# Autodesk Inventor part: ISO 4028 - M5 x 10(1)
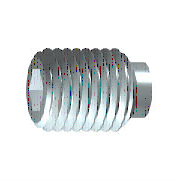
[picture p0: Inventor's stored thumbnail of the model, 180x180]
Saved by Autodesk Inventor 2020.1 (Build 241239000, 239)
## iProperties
Created: 2019-01
Part Number: ISO 4028 - M5 x 10(1)
Material: Edelstahl, 440C
Description: Innensechskant-Gewindestifte mit Zapfen
Document SubType Name: Modeling
Standard: ISO 4028
Designer: lutzd
Standard Revision: Third edition 2003-12-01
Standards Organization: ISO
Language: de-DE
Size Designation: M5 x 10
Categories: <MemberInstance><Categories><Category DisplayName="Verbindungselemente" InternalName="e4da775c-781d-43d5-af7c-5136215cf5a6" Mnemonic="FSTN"><Category DisplayNam
Mass: 1.14363 g
Surface Area: 1.9956 cm^2
Volume: 0.147565 cm^3
Density: 7.75 g/cm^3
Appearance: Halbpoliert
IsCustomPart: 0
Author: lutzd
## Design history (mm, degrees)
sketch "Skizze1"
  geometry: L1 (0, 0)-(6.167, 0); L2 (10, 1.443)-(10, 2.5); L3 (10, 2.5)-(2.5, 2.5); L4 (10, 1.443)-(7, 1.443); L5 (7, 1.443)-(6.167, 0); L6 (0, -0.5)-(0, 3) reference; L7 (0, 1.75)-(0, 0); L8 (0, 1.75)-(2.5, 1.75); L9 (2.5, 1.75)-(2.5, 2.5)
  constraints: 17 end point, 3 parallel, 3 perpendicular, 1 collinear, 1 point on line
  dimensions: "d0" = 3 distance of L2.start L4.end (= INTI); "d1" = 60 deg angle of L5 L1; "d2" = 5 diameter of L3 L1 (= NND); "d3" = 2.88675 diameter of L4 L1 (= 1.1547 x SW); "d5" = 10 distance from line of L2 L7.start (= NLG); "d7" = 3.5 diameter of L7.start L1 (= SPD); "d14" = 2.5 distance of L7.start L8.end (= ZLG)
revolve "Körper" sketch "Skizze1" stored, may be unused: angle "d6" = 90 deg
sketch "Skizze2"
  geometry: L1 (-0.722, 1.25)-(0.722, 1.25); L2 (0.722, 1.25)-(1.443, 0); L3 (1.443, 0)-(0.722, -1.25); L4 (0.722, -1.25)-(-0.722, -1.25); L5 (-0.722, -1.25)-(-1.443, 0); L6 (-1.443, 0)-(-0.722, 1.25); A1 r 1.443 centre (0, 0) between (-0.722, 1.25) and (0.722, 1.25) reference; 2 further points
  constraints: 12 end point, 2 point on circle, 1 coincident, 1 horizontal, 11 other
extrude "Loch" join sketch "Skizze2" taper "d10" = 0 deg; stored distance "d21" = 10
workaxis "Work Axis1"
workplane "Work Plane1"
body "Solid1"
chamfer "Fase1" distance "d8" = 0.49076 (computed from NND, GD1, FAWI); stored, may be unused: angle "d9" = 45 deg (= FAWI), second distance "d30" = 0.49076 (computed from NND, GD1, FAWI)
feature "Gewinde" dims "d12" = 7.5 (= NLG - ZLG), "d13" = 0
chamfer "Fase2" distance "d15" = 0.75 (computed from NND, SPD, FAWI1); stored, may be unused: angle "d16" = 45 deg (= FAWI1), second distance "d31" = 0.75 (computed from NND, SPD, FAWI1)
other parameters: "NND" = 5 [user parameter; used in 5 equation terms], "NLG" = 10 [user parameter; used in 2 equation terms], "INTI" = 3 [user parameter; used in 1 equation term], "FAWI" = 45 deg [user parameter; used in 3 equation terms], "SW" = 2.5 [user parameter; used in 2 equation terms], "GD1" = 4.01848 (= THREADDIA - 1.2269 x PTC) [user parameter; used in 2 equation terms], "d4" = 0, "FAWI1" = 45 deg [user parameter; used in 3 equation terms], "SPD" = 3.5 [user parameter; used in 3 equation terms], "ZLG" = 2.5 [user parameter; used in 2 equation terms], "d32" = 0, "d33" = 0, "GUL" = 0.49076 (= 0.61345 x PTC) [user parameter], "TPU" = 12.5 (computed from PTC) [user parameter], "TOA" = 30 deg [user parameter], "THREADDIA" = 5 [user parameter; used in 1 equation term], "PTC" = 0.8 [user parameter; used in 4 equation terms], "GAL" = 0.49076 (= 0.61345 x PTC) [user parameter], "E0" = 2.8875 (= 1.155 x SW) [user parameter]
